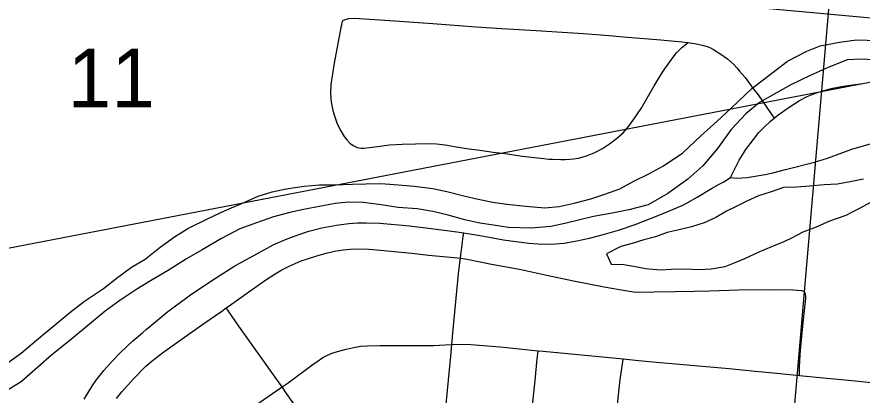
# Model space of a CAD drawing. Extents: x 0 to 34, y 0 to 22.
# Drawn here: x 7.471 to 8.075, y 19.937 to 20.207 of the extents above; entities that cross this region are included whole.
import ezdxf

# ---------------------------------------------------------------- set-up
doc = ezdxf.new("R2010")
doc.units = 0
for name, color, linetype in [('GM_X_City_Street', 7, 'Continuous'), ('GM_X_Corporation', 7, 'Continuous'), ('GM_X_Major_River', 7, 'Continuous'), ('GM_X_Minor_Lake', 7, 'Continuous'), ('GM_X_Rail_Line', 7, 'Continuous'), ('GM_X_Section_Text', 7, 'Continuous'), ('SH_Text', 7, 'Continuous')]:
    doc.layers.add(name, color=color, linetype=linetype)

msp = doc.modelspace()

# ---------------------------------------------------------------- linework, layer by layer
at = {"layer": 'GM_X_City_Street'}
for points in [[(7.70415, 20.20429), (7.70571, 20.20511), (7.70842, 20.20577), (7.71212, 20.2061), (7.71607, 20.20582), (7.73761, 20.20444), (7.76841, 20.20217), (7.78688, 20.20081), (7.79921, 20.19991), (7.81771, 20.19873), (7.83004, 20.19802), (7.84225, 20.1973), (7.86074, 20.19607), (7.87611, 20.195), (7.89444, 20.1936), (7.9071, 20.19237), (7.92847, 20.19081), (7.94681, 20.18905), (7.94989, 20.18878), (7.9507, 20.18864)], [(7.70415, 20.20429), (7.70349, 20.20289), (7.70308, 20.20108), (7.70275, 20.19935), (7.69794, 20.17396), (7.69562, 20.1586), (7.69536, 20.15239), (7.69545, 20.14928), (7.69576, 20.1462), (7.69694, 20.14011), (7.6978, 20.13712), (7.69886, 20.13418), (7.6999, 20.13131), (7.70127, 20.12834), (7.70275, 20.12554), (7.70513, 20.12166), (7.70689, 20.11914), (7.709, 20.11688), (7.71146, 20.11505), (7.71427, 20.11375), (7.71713, 20.11318), (7.71909, 20.11326), (7.7252, 20.11392), (7.73751, 20.11562), (7.74656, 20.11608), (7.75593, 20.11641), (7.7653, 20.11658), (7.77089, 20.11641), (7.77714, 20.11559), (7.78396, 20.11444), (7.79251, 20.11305), (7.80197, 20.11173), (7.81158, 20.1105), (7.82005, 20.10943), (7.8323, 20.10762), (7.84775, 20.10581), (7.85129, 20.10548), (7.85383, 20.1054), (7.85984, 20.10515), (7.86296, 20.10515), (7.86633, 20.10532), (7.86896, 20.10556), (7.87241, 20.10614), (7.87824, 20.10784), (7.88401, 20.11016), (7.88951, 20.11303), (7.89468, 20.11642), (7.89962, 20.12012), (7.90424, 20.12425), (7.90835, 20.12888), (7.91206, 20.13386), (7.91716, 20.14165), (7.92652, 20.1577), (7.93298, 20.16819), (7.93648, 20.17329), (7.94007, 20.17831), (7.94245, 20.18127), (7.94631, 20.18522), (7.9507, 20.18864)], [(7.9507, 20.18864), (7.95782, 20.18744), (7.96078, 20.18678), (7.96423, 20.1858), (7.96678, 20.18481), (7.96888, 20.18373), (7.97147, 20.1821), (7.97406, 20.18045), (7.97656, 20.17876), (7.97896, 20.17695), (7.98123, 20.17498), (7.98337, 20.17287), (7.98541, 20.17062), (7.98739, 20.1683), (7.99136, 20.16376), (7.99695, 20.1562), (8.00064, 20.15127), (8.0101, 20.13771), (8.01217, 20.13474)], [(7.98102, 20.09221), (7.98706, 20.10465), (7.99199, 20.11238), (7.99733, 20.11945), (8.00125, 20.12434), (8.00531, 20.12849), (8.00966, 20.1326), (8.01217, 20.13474), (8.01468, 20.13687), (8.02208, 20.14214), (8.03022, 20.14731), (8.03572, 20.15019), (8.04172, 20.1525), (8.04756, 20.15447), (8.05397, 20.15603), (8.06277, 20.15775), (8.07543, 20.15932)], [(7.98102, 20.09221), (7.98546, 20.09178), (7.99285, 20.09229), (8.00568, 20.09443), (8.01127, 20.09575), (8.02023, 20.09796), (8.04109, 20.1032), (8.05023, 20.1061), (8.06774, 20.11243), (8.08163, 20.11662), (8.08599, 20.11785), (8.10983, 20.1237), (8.11928, 20.12526), (8.12627, 20.12591), (8.13235, 20.12591), (8.13827, 20.12583), (8.14411, 20.12575), (8.16137, 20.12427), (8.16372, 20.12406)], [(7.51947, 19.9341), (7.52533, 19.94378), (7.52804, 19.94764), (7.53075, 19.95127), (7.53339, 19.95455), (7.53938, 19.96113), (7.54531, 19.96746), (7.5541, 19.97568), (7.56092, 19.98151), (7.56355, 19.98381), (7.56618, 19.98604), (7.57917, 19.99656), (7.5952, 20.00848), (7.60992, 20.01826), (7.62702, 20.02919), (7.64313, 20.03815), (7.65439, 20.04423), (7.6631, 20.04818), (7.67075, 20.05089), (7.67987, 20.05393), (7.68916, 20.0564), (7.69952, 20.05829), (7.7084, 20.05952), (7.71464, 20.05985), (7.72105, 20.05994), (7.73042, 20.05969), (7.75163, 20.05771), (7.76725, 20.05599), (7.77645, 20.05475), (7.7855, 20.05352), (7.79045, 20.05283), (7.79174, 20.05265), (7.80082, 20.05123), (7.81878, 20.04789), (7.82775, 20.04661), (7.83696, 20.04547), (7.84329, 20.04489), (7.84929, 20.04473), (7.8557, 20.04489), (7.86219, 20.04547), (7.87115, 20.04703), (7.88028, 20.04892), (7.88932, 20.0513), (7.90108, 20.05484), (7.91283, 20.05887), (7.9305, 20.06577), (7.94637, 20.07243), (7.94998, 20.07423), (7.95714, 20.07835), (7.96733, 20.08443), (7.97284, 20.08756), (7.97617, 20.08933), (7.98102, 20.09221)], [(7.77562, 19.90582), (7.77887, 19.94026), (7.78123, 19.96471), (7.78198, 19.97308), (7.78295, 19.98392), (7.78683, 20.02359), (7.7877, 20.0313), (7.78804, 20.03471), (7.78865, 20.03932), (7.78903, 20.04219), (7.78958, 20.04629), (7.79011, 20.05032), (7.79045, 20.05283)], [(7.54249, 19.93458), (7.54619, 19.93945), (7.55449, 19.94864), (7.56324, 19.95744), (7.56786, 19.96152), (7.57519, 19.9672), (7.58538, 19.97427), (7.60493, 19.98807), (7.61764, 19.997), (7.6208, 19.99928), (7.62462, 20.00202), (7.63689, 20.01073), (7.64917, 20.01931), (7.65578, 20.02366), (7.66064, 20.02649), (7.6658, 20.02911), (7.67437, 20.03275), (7.67895, 20.03427), (7.68549, 20.03645), (7.69217, 20.03834), (7.69812, 20.03964), (7.70444, 20.04073), (7.70953, 20.04117), (7.71563, 20.04139), (7.7226, 20.04117), (7.72848, 20.04066), (7.74069, 20.0395), (7.75348, 20.03826), (7.76539, 20.03696), (7.77838, 20.03568), (7.78369, 20.03514), (7.78804, 20.03471)], [(7.78804, 20.03471), (7.79284, 20.03404), (7.81028, 20.03056), (7.83149, 20.02657), (7.8487, 20.02287), (7.8689, 20.01865), (7.89076, 20.01437), (7.9018, 20.01233), (7.91175, 20.01081), (7.91524, 20.01059), (7.92643, 20.01073), (7.94147, 20.01102), (7.95527, 20.01124), (7.96602, 20.01153), (7.98701, 20.01204), (8.01141, 20.01248), (8.02546, 20.01217), (8.02868, 20.01197), (8.03168, 20.01156), (8.03377, 20.0109)], [(8.0303, 19.95099), (8.0303, 19.95444), (8.03023, 19.95676), (8.03081, 19.96599), (8.0314, 19.97415), (8.03313, 19.99098), (8.03476, 20.00589), (8.0348, 20.00768), (8.03453, 20.00915), (8.03377, 20.0109)], [(7.74829, 19.8157), (7.74488, 19.82134), (7.7429, 19.82455), (7.739, 19.83104), (7.72927, 19.84495), (7.70812, 19.87551), (7.70206, 19.88427), (7.69963, 19.88766), (7.69596, 19.89277), (7.68523, 19.90783), (7.66384, 19.93816), (7.66067, 19.94283), (7.65827, 19.94638), (7.62987, 19.98617), (7.6225, 19.99682), (7.6208, 19.99928)], [(7.62913, 19.92099), (7.65703, 19.94037), (7.66067, 19.94283), (7.665, 19.94576), (7.68191, 19.95836), (7.68568, 19.96095), (7.68988, 19.96385), (7.69322, 19.96561), (7.69699, 19.96709), (7.70126, 19.96842), (7.70649, 19.96982), (7.71088, 19.97075), (7.71681, 19.97183), (7.72176, 19.97226), (7.73049, 19.97236), (7.74675, 19.97247), (7.7614, 19.97247), (7.76915, 19.97247), (7.77712, 19.9728), (7.78198, 19.97308), (7.78832, 19.97344), (7.79554, 19.97322), (7.8165, 19.97139), (7.84352, 19.96865), (7.84724, 19.96827), (7.90435, 19.96279), (7.91521, 19.96174), (7.93064, 19.96028), (7.9801, 19.95589), (7.99861, 19.95417), (8.01402, 19.95266), (8.0303, 19.95099), (8.04488, 19.94949), (8.06534, 19.94759), (8.08887, 19.94532)], [(7.8228, 19.75063), (7.82302, 19.75278), (7.826, 19.7813), (7.82848, 19.80586), (7.82997, 19.82325), (7.8303, 19.82802), (7.83104, 19.8386), (7.83156, 19.84595), (7.83185, 19.8506), (7.83248, 19.8582), (7.83465, 19.8797), (7.8358, 19.89047), (7.83627, 19.89585), (7.83683, 19.90204), (7.83983, 19.93206), (7.84139, 19.94746), (7.84293, 19.96286), (7.84352, 19.96865)], [(7.88002, 19.74642), (7.88129, 19.74762), (7.88203, 19.74859), (7.88244, 19.74961), (7.88265, 19.75047), (7.88405, 19.76321), (7.88602, 19.78194), (7.8878, 19.79922), (7.8902, 19.82267), (7.89061, 19.82697), (7.89127, 19.83275), (7.89248, 19.84476), (7.89571, 19.87621), (7.89697, 19.88988), (7.89742, 19.89472), (7.89908, 19.91633), (7.90067, 19.93481), (7.90224, 19.94818), (7.90403, 19.96064), (7.90435, 19.96279)]]:
    msp.add_lwpolyline(points, dxfattribs=at)
at = {"layer": 'GM_X_Corporation'}
for points in [[(7.08216, 20.72429), (8.08658, 20.62681), (8.00052, 19.62676), (6.98964, 19.72208)], [(8.84939, 19.54367), (8.84939, 20.54888), (8.08658, 20.62681), (8.00052, 19.62676)]]:
    msp.add_lwpolyline(points, close=True, dxfattribs=at)
at = {"layer": 'GM_X_Major_River'}
for points in [[(7.46432, 19.95969), (7.47436, 19.96705), (7.48521, 19.9763), (7.49799, 19.98664), (7.50921, 19.99587), (7.51966, 20.00399), (7.53316, 20.01317), (7.54321, 20.02091), (7.55326, 20.02828), (7.56289, 20.03413), (7.57372, 20.04262), (7.58376, 20.04998), (7.59339, 20.05584), (7.60799, 20.0631), (7.61951, 20.06852), (7.63254, 20.07392), (7.64367, 20.07898), (7.65361, 20.08216), (7.66353, 20.08421), (7.67648, 20.08618), (7.68751, 20.08706), (7.69776, 20.0872), (7.71106, 20.08765), (7.72055, 20.0878), (7.73118, 20.08794), (7.74065, 20.08733), (7.75505, 20.08623), (7.76829, 20.0844), (7.77849, 20.08226), (7.79056, 20.07931), (7.80075, 20.07679), (7.81132, 20.07464), (7.82116, 20.07327), (7.83479, 20.07181), (7.84843, 20.07073), (7.85869, 20.07162), (7.86938, 20.07403), (7.88122, 20.07718), (7.89117, 20.08036), (7.90189, 20.08429), (7.91189, 20.08975), (7.92264, 20.09482), (7.93302, 20.10065), (7.94691, 20.10983), (7.95972, 20.12207), (7.97136, 20.13243), (7.98145, 20.14169), (7.99621, 20.15579), (8.01052, 20.16685), (8.02173, 20.17533), (8.03557, 20.1826), (8.04514, 20.18618), (8.05887, 20.18889), (8.07105, 20.1905), (8.08623, 20.19015)], [(8.08703, 20.17606), (8.07452, 20.17674), (8.06426, 20.17622), (8.05085, 20.17084), (8.0378, 20.16507), (8.02398, 20.15855), (8.01437, 20.15308), (8.00166, 20.14578), (7.99198, 20.13765), (7.98147, 20.12649), (7.97165, 20.11304), (7.96111, 20.10075), (7.95063, 20.09112), (7.93634, 20.08081), (7.92211, 20.07279), (7.90836, 20.06931), (7.89654, 20.06693), (7.8832, 20.06459), (7.87327, 20.06216), (7.86258, 20.05937), (7.85266, 20.05733), (7.83859, 20.05614), (7.82228, 20.05652), (7.81169, 20.05829), (7.80186, 20.05966), (7.79129, 20.06219), (7.77922, 20.06552), (7.76828, 20.06806), (7.75731, 20.06984), (7.74368, 20.07092), (7.73157, 20.07272), (7.71871, 20.07455), (7.70809, 20.0748), (7.69858, 20.07388), (7.68866, 20.07183), (7.67608, 20.06947), (7.66616, 20.06742), (7.6547, 20.06427), (7.64245, 20.06), (7.63059, 20.05572), (7.61752, 20.04881), (7.60366, 20.04077), (7.59249, 20.0342), (7.58016, 20.02651), (7.56669, 20.01846), (7.55706, 20.01261), (7.54472, 20.00454), (7.53429, 19.9968), (7.52035, 19.98535), (7.51066, 19.97722), (7.49596, 19.9654), (7.48626, 19.95689), (7.47425, 19.94653), (7.46384, 19.93994)]]:
    msp.add_lwpolyline(points, dxfattribs=at)
at = {"layer": 'GM_X_Minor_Lake'}
for points in [[(8.07593, 20.09111), (8.06646, 20.08928), (8.05737, 20.08745), (8.0479, 20.08715), (8.03768, 20.08608), (8.02822, 20.08539), (8.01876, 20.08508), (8.01004, 20.08211), (8.00093, 20.07914), (7.99258, 20.07541), (7.98461, 20.07129)], [(8.06822, 20.06776), (8.07236, 20.06988), (8.0811, 20.07475)], [(7.98461, 20.07129), (7.97815, 20.06831), (7.97055, 20.06381), (7.9622, 20.06008), (7.9531, 20.05711), (7.94438, 20.0549), (7.93566, 20.05306), (7.92732, 20.05009), (7.91898, 20.04787), (7.91064, 20.04528), (7.90267, 20.04306), (7.89242, 20.03782)], [(7.89242, 20.03782), (7.89577, 20.03058), (7.90484, 20.03014), (7.91429, 20.02855), (7.92033, 20.02737), (7.93092, 20.02653), (7.93887, 20.02685), (7.9487, 20.02716), (7.95854, 20.0267), (7.96724, 20.02702), (7.97709, 20.02884), (7.98544, 20.0322), (7.99113, 20.03443), (8.00138, 20.03929), (8.01049, 20.04302), (8.01922, 20.04675), (8.02491, 20.04936), (8.03289, 20.05348), (8.04238, 20.0572), (8.05187, 20.06131), (8.06362, 20.0654), (8.06822, 20.06776)]]:
    msp.add_lwpolyline(points, dxfattribs=at)
at = {"layer": 'GM_X_Rail_Line'}
msp.add_lwpolyline([(7.48232, 20.29421), (7.48749, 20.28896), (7.49472, 20.2834), (7.52452, 20.26748), (7.57443, 20.25347), (7.67337, 20.24253), (7.99809, 20.21388), (8.15925, 20.19925), (8.24374, 20.18913), (8.60421, 20.11965), (8.71999, 20.10062), (8.77096, 20.10215), (8.84859, 20.10474), (8.84939, 20.10462)], dxfattribs=at)
at = {"layer": 'SH_Text'}
msp.add_lwpolyline([(9.4782, 20.78964), (4.28936, 19.4307), (9.4782, 20.42968)], close=True, dxfattribs=at)

# ---------------------------------------------------------------- texts
at = {"layer": 'GM_X_Section_Text'}
msp.add_text('11', height=0.041856, rotation=0.00001, dxfattribs=at).set_placement((7.50762, 20.14243))

doc.saveas('drawing.dxf')
